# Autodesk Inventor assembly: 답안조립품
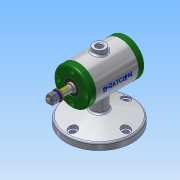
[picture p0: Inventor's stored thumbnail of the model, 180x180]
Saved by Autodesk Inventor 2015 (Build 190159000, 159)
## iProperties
Created: 2018-12
Part Number: 답안조립품
Document SubType Name: Assembly
Designer: 405-10
Author: 405-10
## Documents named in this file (13)
- C:\Users\405-10\Desktop\481207V1058\답안조립품.iam
- C:\Users\405-10\Desktop\481207V1058\본체.ipt
- C:\Users\405-10\Desktop\481207V1058\앞커버.ipt
- C:\Users\405-10\Desktop\481207V1058\뒤커버.ipt
- C:\Users\405-10\Desktop\481207V1058\축.ipt
- C:\Users\405-10\Desktop\481207V1058\베어링 15 x 32 x 9.ipt
- C:\Users\405-10\Desktop\481207V1058\오일 실 15 25 7.ipt
- C:\Users\405-10\Desktop\481207V1058\키 3 x 3 x 12.ipt
- C:\Users\405-10\Desktop\481207V1058\V벨트풀리.ipt
- C:\Users\405-10\Desktop\481207V1058\와셔 8x17.ipt
- C:\Users\405-10\Desktop\481207V1058\스프링와셔 8.ipt
- C:\Users\405-10\Desktop\481207V1058\너트 M8.ipt
- 너트 M8.ipt
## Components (1 placed, 1 different names)
1. V벨트풀리:1
